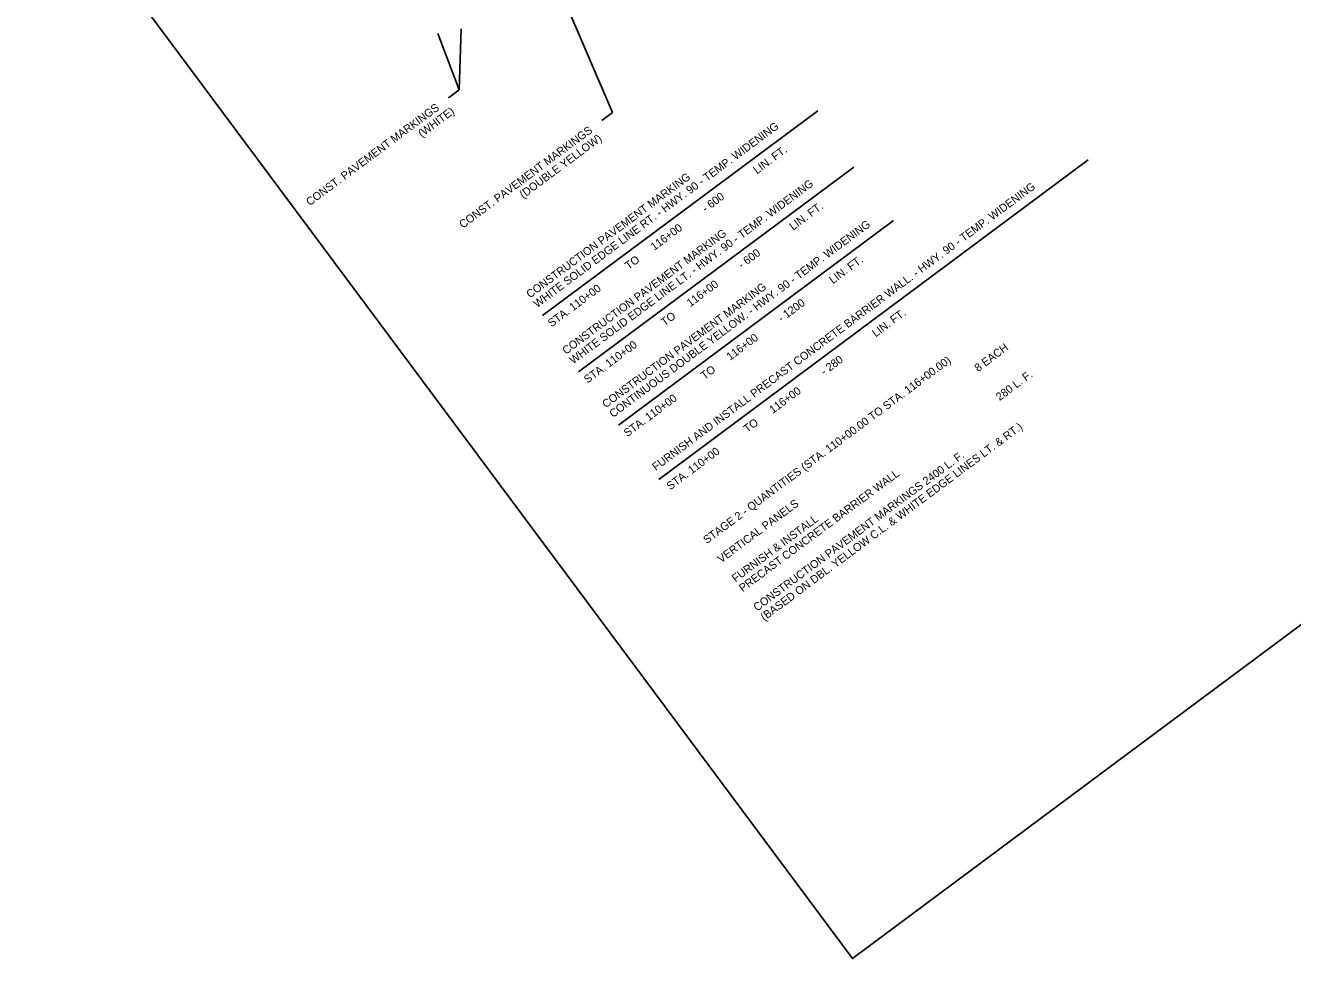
# Model space of a CAD drawing. Extents: x 1571137 to 1573037, y 731597 to 733451.
# Drawn here: x 1571137 to 1572087, y 731597 to 732297 of the extents above; entities that cross this region are included whole.
import ezdxf

# ---------------------------------------------------------------- set-up
doc = ezdxf.new("R2010")
doc.units = 0
doc.layers.add('R_Annotation', color=7, linetype='Continuous')
doc.layers.add('R_Horz Alg Annot', color=7, linetype='Continuous')

msp = doc.modelspace()

# ---------------------------------------------------------------- linework, layer by layer
at = {"layer": 'R_Annotation'}
for p, q in [((1571539.47, 732318.97), (1571576.97, 732231.31)), ((1571446.21, 732290.6), (1571462.2, 732248.26)), ((1571463.72, 732294.1), (1571462.2, 732248.26)), ((1571454.18, 732242.29), (1571462.2, 732248.26)), ((1571524.65, 732079.26), (1571730.85, 732232.72)), ((1571568.95, 732225.34), (1571576.97, 732231.31)), ((1571611.71, 731956.38), (1571933.49, 732195.86)), ((1571551.67, 732037.04), (1571757.87, 732190.5)), ((1571581.53, 731996.93), (1571787.72, 732150.39))]:
    msp.add_line(p, q, dxfattribs=at)
at = {"layer": 'R_Horz Alg Annot'}
msp.add_lwpolyline([(1572536.74, 733221.56), (1573036.71, 732549.76), (1571756.88, 731597.29), (1571136.98, 732430.24), (1572086.85, 733137.16), (1572116.34, 733097.53), (1572258.81, 733203.56), (1572269.47, 733189.25), (1572284.07, 733200.11), (1572282.13, 733202.72), (1572344.44, 733249.09)], dxfattribs=at)

# ---------------------------------------------------------------- texts
at = {"layer": 'R_Annotation'}
for s, p in [('CONST. PAVEMENT MARKINGS', (1571350.16, 732161.13)), ('(WHITE)', (1571434.14, 732212.41)), ('WHITE SOLID EDGE LINE RT. - HWY. 90 - TEMP. WIDENING', (1571520.6, 732084.71)), ('CONST. PAVEMENT MARKINGS', (1571464.93, 732144.19)), ('(DOUBLE YELLOW)', (1571510.17, 732166.64)), ('LIN. FT.', (1571685.37, 732184.9)), ('CONSTRUCTION PAVEMENT MARKING', (1571515.22, 732091.93)), ('WHITE SOLID EDGE LINE LT. - HWY. 90 - TEMP. WIDENING', (1571547.62, 732042.5)), ('FURNISH AND INSTALL PRECAST CONCRETE BARRIER WALL. - HWY. 90 - TEMP. WIDENING', (1571609.55, 731962.57)), ('- 600 ', (1571646.86, 732156.25)), ('LIN. FT.', (1571712.39, 732142.69)), ('CONTINUOUS DOUBLE YELLOW. - HWY. 90 - TEMP. WIDENING', (1571577.47, 732002.38)), ('116+00', (1571608.35, 732127.59)), ('CONSTRUCTION PAVEMENT MARKING', (1571542.24, 732049.72)), ('- 600 ', (1571673.88, 732114.03)), ('TO', (1571589.1, 732113.26)), ('LIN. FT.', (1571742.24, 732102.57)), ('STA. 110+00', (1571531.34, 732070.27)), ('CONSTRUCTION PAVEMENT MARKING', (1571572.09, 732009.6)), ('116+00', (1571635.38, 732085.37)), ('- 1200 ', (1571703.73, 732073.92)), ('TO', (1571616.12, 732071.04)), ('LIN. FT.', (1571774.32, 732062.76)), ('116+00', (1571665.23, 732045.26)), ('STA. 110+00', (1571558.36, 732028.06)), ('8 EACH ', (1571851.08, 732036.72)), ('STAGE 2 - QUANTITIES (STA. 110+00.00 TO STA. 116+00.00)', (1571647.8, 731907.88)), ('- 280 ', (1571735.81, 732034.1)), ('TO', (1571645.97, 732030.93)), ('280 L. F.', (1571867.2, 732015.06)), ('116+00', (1571697.31, 732005.45)), ('STA. 110+00', (1571588.21, 731987.94)), ('TO', (1571678.05, 731991.12)), ('(BASED ON DBL. YELLOW C.L. & WHITE EDGE LINES LT. & RT.)', (1571690.79, 731850.12)), ('STA. 110+00', (1571620.3, 731948.13)), ('CONSTRUCTION PAVEMENT MARKINGS 2400 L. F. ', (1571685.42, 731857.34)), ('PRECAST CONCRETE BARRIER WALL ', (1571674.67, 731871.78)), ('VERTICAL PANELS ', (1571658.55, 731893.44)), ('FURNISH & INSTALL', (1571669.3, 731879))]:
    msp.add_text(s, height=6, rotation=36.65758, dxfattribs=at).set_placement(p)

doc.saveas('drawing.dxf')
